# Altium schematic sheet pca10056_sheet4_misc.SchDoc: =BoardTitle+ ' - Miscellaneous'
size A3; Organization: Nordic Semiconductor; DocumentNumber: 4; SheetNumber: 4; SheetTotal: 6; CompanyName: Nordic Semiconductor; DocumentSize: A3
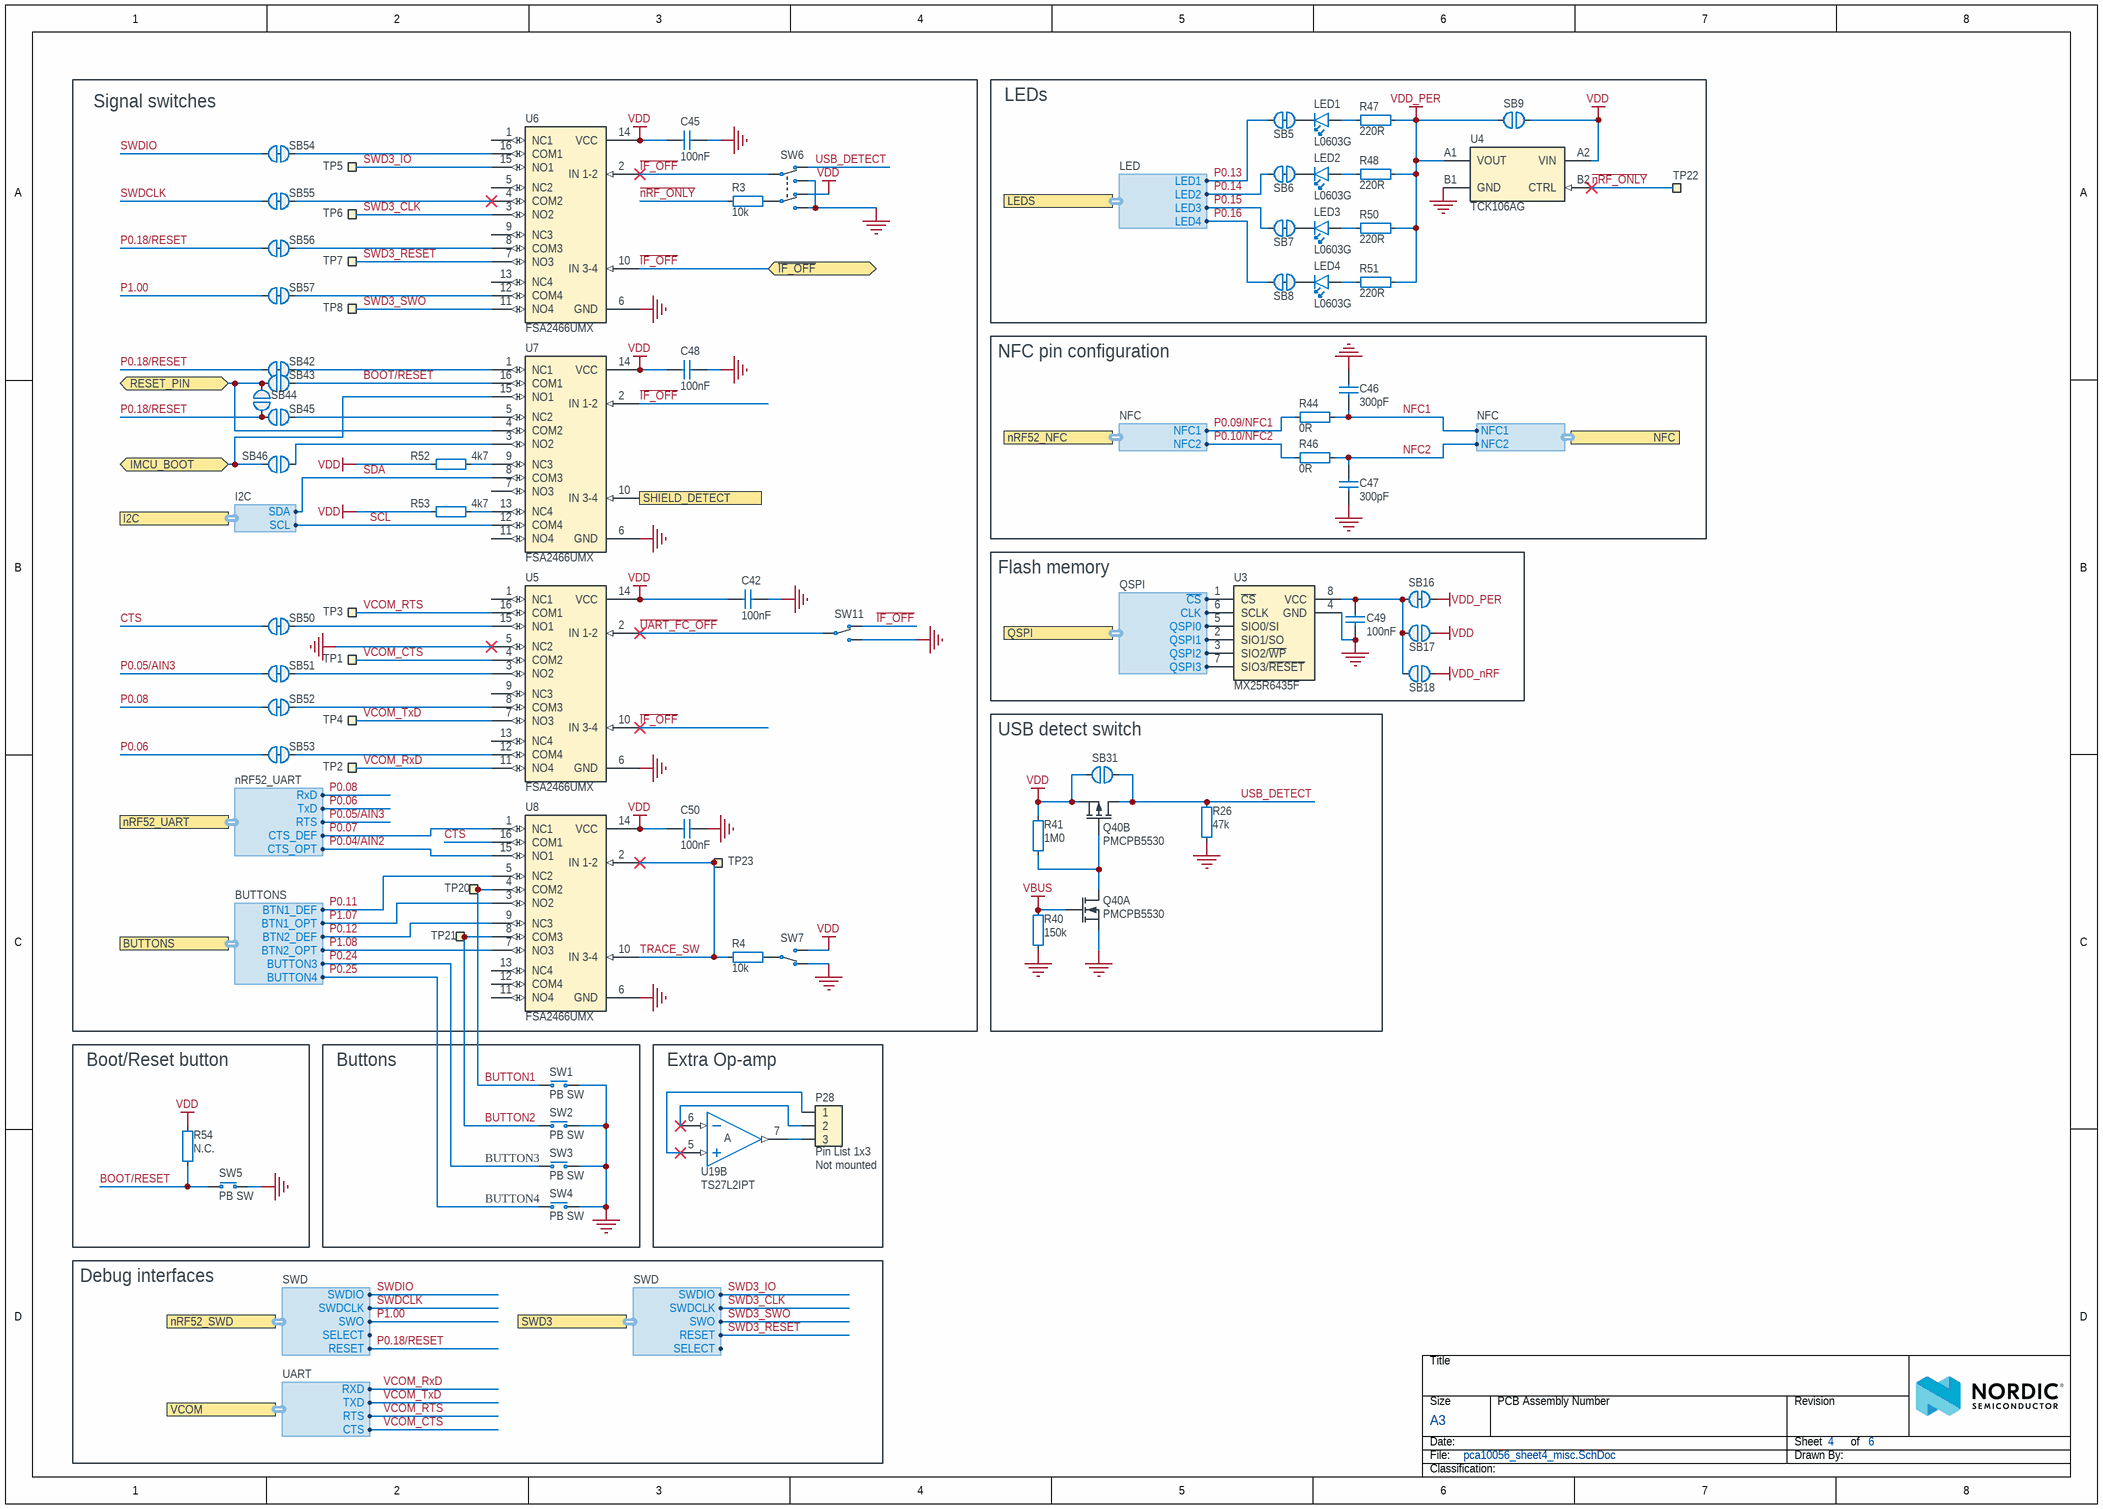
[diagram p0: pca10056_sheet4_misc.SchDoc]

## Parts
C42  100nF  [CAPC0603X03L_C]
C45  100nF  [CAPC0603X03L_C]
C46  300pF  [CAPC1005X04L]
C47  300pF  [CAPC1005X04L]
C48  100nF  [CAPC0603X03L_C]
C49  100nF  [CAPC0603X03L_C]
C50  100nF  [CAPC0603X03L_C]
LED1  L0603G  [LED_0603_G]
LED2  L0603G  [LED_0603_G]
LED3  L0603G  [LED_0603_G]
LED4  L0603G  [LED_0603_G]
P28  Pin List 1x3  Assembly: Not mounted  [LIST_1x3-NC]
Q40  PMCPB5530  [PMCPB5530X]  (parts A,B of 2)
R3  10k  [RESC0603X03L_C]
R4  10k  [RESC0603X03L_C]
R26  47k  [RESC0603X03L_C]
R40  150k  [RESC0603X03L_C]
R41  1M0  [RESC0603X03L_C]
R44  0R  [RESC1005X04L]
R46  0R  [RESC1005X04L]
R47  220R  [RESC0603X03L_C]
R48  220R  [RESC0603X03L_C]
R50  220R  [RESC0603X03L_C]
R51  220R  [RESC0603X03L_C]
R52  4k7  [RESC0603X03L_C]
R53  4k7  [RESC0603X03L_C]
R54  N.C.  [RESC0603X03L_C_NC]
SB5  Solderbridge  [Solderbridge_Shorted]  (value not drawn)  (net tie, no BOM)
SB6  Solderbridge  [Solderbridge_Shorted]  (value not drawn)  (net tie, no BOM)
SB7  Solderbridge  [Solderbridge_Shorted]  (value not drawn)  (net tie, no BOM)
SB8  Solderbridge  [Solderbridge_Shorted]  (value not drawn)  (net tie, no BOM)
SB9  Solderbridge  [Solderbridge]  (value not drawn)  (no BOM)
SB16  Solderbridge  [Solderbridge_Shorted]  (value not drawn)  (net tie, no BOM)
SB17  Solderbridge  [Solderbridge]  (value not drawn)  (no BOM)
SB18  Solderbridge  [Solderbridge]  (value not drawn)  (no BOM)
SB31  Solderbridge  [Solderbridge]  (value not drawn)  (no BOM)
SB42  Solderbridge  [Solderbridge_Shorted]  (value not drawn)  (net tie, no BOM)
SB43  Solderbridge  [Solderbridge]  (value not drawn)  (no BOM)
SB44  Solderbridge  [Solderbridge]  (value not drawn)  (no BOM)
SB45  Solderbridge  [Solderbridge]  (value not drawn)  (no BOM)
SB46  Solderbridge  [Solderbridge]  (value not drawn)  (no BOM)
SB50  Solderbridge  [Solderbridge_Shorted]  (value not drawn)  (net tie, no BOM)
SB51  Solderbridge  [Solderbridge_Shorted]  (value not drawn)  (net tie, no BOM)
SB52  Solderbridge  [Solderbridge_Shorted]  (value not drawn)  (net tie, no BOM)
SB53  Solderbridge  [Solderbridge_Shorted]  (value not drawn)  (net tie, no BOM)
SB54  Solderbridge  [Solderbridge_Shorted]  (value not drawn)  (net tie, no BOM)
SB55  Solderbridge  [Solderbridge_Shorted]  (value not drawn)  (net tie, no BOM)
SB56  Solderbridge  [Solderbridge_Shorted]  (value not drawn)  (net tie, no BOM)
SB57  Solderbridge  [Solderbridge_Shorted]  (value not drawn)  (net tie, no BOM)
SW1  PB SW  [Switch-PB-6.2x6.3mm-SMD]
SW2  PB SW  [Switch-PB-6.2x6.3mm-SMD]
SW3  PB SW  [Switch-PB-6.2x6.3mm-SMD]
SW4  PB SW  [Switch-PB-6.2x6.3mm-SMD]
SW5  PB SW  [Switch-PB-6.2x6.3mm-SMD]
SW6  MKH-22D14-G2-B  [MKH-22D14-G2-B]  (value not drawn)
SW7  Switch  [CJS-120xA]  (value not drawn)
SW11  Switch  [CJS-120xA]  (value not drawn)
TP1  Ø1.0mm,SMD  [TP_SMD_D1.0mm]  (value not drawn)  (no BOM)
TP2  Ø1.0mm,SMD  [TP_SMD_D1.0mm]  (value not drawn)  (no BOM)
TP3  Ø1.0mm,SMD  [TP_SMD_D1.0mm]  (value not drawn)  (no BOM)
TP4  Ø1.0mm,SMD  [TP_SMD_D1.0mm]  (value not drawn)  (no BOM)
TP5  Ø1.0mm,SMD  [TP_SMD_D1.0mm]  (value not drawn)  (no BOM)
TP6  Ø1.0mm,SMD  [TP_SMD_D1.0mm]  (value not drawn)  (no BOM)
TP7  Ø1.0mm,SMD  [TP_SMD_D1.0mm]  (value not drawn)  (no BOM)
TP8  Ø1.0mm,SMD  [TP_SMD_D1.0mm]  (value not drawn)  (no BOM)
TP20  Ø1.0mm,SMD  [TP_SMD_D1.0mm]  (value not drawn)  (no BOM)
TP21  Ø1.0mm,SMD  [TP_SMD_D1.0mm]  (value not drawn)  (no BOM)
TP22  Ø1.0mm,SMD  [TP_SMD_D1.0mm]  (value not drawn)  (no BOM)
TP23  Ø1.0mm,SMD  [TP_SMD_D1.0mm]  (value not drawn)  (no BOM)
U3  MX25R6435F  [SON127P600X80_HS-9N]
U4  TCK106AG  [BGA4C40P2X2_76X76X62]
U5  FSA2466UMX  [XQFN40P180X260X50-16N]
U6  FSA2466UMX  [XQFN40P180X260X50-16N]
U7  FSA2466UMX  [XQFN40P180X260X50-16N]
U8  FSA2466UMX  [XQFN40P180X260X50-16N]
U19  TS27L2IPT  [TSOP65P640X120-8N]  (part B of 2)

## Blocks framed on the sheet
Signal switches: C42 C45 C48 C50 R3 R4 R52 R53 SB42-SB46 SB50-SB57 SW6 SW7 SW11 TP1-TP8 TP20 TP21 TP23 U5-U8
LEDs: LED1-LED4 R47 R48 R50 R51 SB5-SB9 TP22 U4
NFC pin configuration: C46 C47 R44 R46
Flash memory: C49 SB16-SB18 U3
USB detect switch: Q40 R26 R40 R41 SB31
Boot/Reset button: R54 SW5
Buttons: SW1-SW4
Extra Op-amp: P28 U19

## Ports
BUTTONS (harness BUTTONS), I2C (harness I2C), IMCU_BOOT (bidir), LEDS (harness LED), NFC (harness NFC), nRF52_NFC (harness NFC), nRF52_SWD (harness SWD), nRF52_UART (harness nRF52_UART), QSPI (harness QSPI), RESET_PIN (bidir), SHIELD_DETECT (in), SWD3 (harness SWD), VCOM (harness UART), ~{IF_OFF} (bidir)

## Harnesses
SWD: SWDIO, SWDCLK, SWO, RESET, SELECT
NFC: NFC2, NFC1
I2C: SCL, SDA
UART: RTS, CTS, RXD, TXD
QSPI: ~{CS}, QSPI0, CLK, QSPI1, QSPI2, QSPI3
LED: LED4, LED3, LED2, LED1
BUTTONS: BTN2_OPT, BTN2_DEF, BTN1_OPT, BTN1_DEF, BUTTON3, BUTTON4
nRF52_UART: RTS, CTS_DEF, CTS_OPT, TxD, RxD

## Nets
GND: C42.1 C45.1 C46.2 C47.1 C48.1 C49.1 C50.1 Q40.1(S1) R26.2 R40.2 SW1.1(N.O) SW2.1(N.O) SW3.1(N.O) SW4.1(N.O) SW5.1(N.O) SW6.1(N.O-1) SW6.4(N.O-2) SW7.1(N.C) SW11.3(N.O) U3.4(GND) U3.9(GND) U4.B1(GND) U5.5(NC2) U5.6(GND) U6.6(GND) U7.6(GND) U8.6(GND)
VBUS: Q40.2(G1) R40.1
VDD: C42.2 C45.2 C48.2 C50.2 Q40.4(S2) R41.1 R52.1 R53.1 R54.2 SB9.1 SB17.1 SB31.1 SW6.6(N.C-2) SW7.3(N.O) U4.A2(VIN) U5.14(VCC) U6.14(VCC) U7.14(VCC) U8.14(VCC)
VDD_nRF: SB18.1
VDD_PER: R47.2 R48.2 R50.2 R51.2 SB9.2 SB16.1 U4.A1(VOUT)
BOOT/RESET: R54.1 SB43.1 SW5.2(COM) U7.16(COM1)
BUTTON1: SW1.2(COM) TP20.1 U8.4(COM2)
BUTTON2: SW2.2(COM) TP21.1 U8.8(COM3)
CTS: SB50.1 U8.16(COM1)
~{IF_OFF}: SW6.2(COM-1) SW11.1(N.C) U5.10(IN_3-4) U6.2(IN_1-2) U6.10(IN_3-4) U7.2(IN_1-2) ; port ~{IF_OFF}
IMCU_BOOT: SB46.2 U7.15(NO1) ; port IMCU_BOOT
~{nRF_ONLY}: R3.1 TP22.1 U4.B2(CTRL)
NFC1: C46.1 R44.1 ; port NFC.NFC1
NFC2: C47.2 R46.1 ; port NFC.NFC2
P0.04/AIN2: U8.15(NO1) ; port nRF52_UART.CTS_OPT
P0.05/AIN3: SB51.1 ; port nRF52_UART.RTS
P0.06: SB53.1 ; port nRF52_UART.TxD
P0.07: U8.1(NC1) ; port nRF52_UART.CTS_DEF
P0.08: SB52.1 ; port nRF52_UART.RxD
P0.09/NFC1: R44.2 ; port nRF52_NFC.NFC1
P0.10/NFC2: R46.2 ; port nRF52_NFC.NFC2
P0.11: U8.5(NC2) ; port BUTTONS.BTN1_DEF
P0.12: U8.9(NC3) ; port BUTTONS.BTN2_DEF
P0.13: SB5.1 ; port LEDS.LED1
P0.14: SB6.1 ; port LEDS.LED2
P0.15: SB7.1 ; port LEDS.LED3
P0.16: SB8.1 ; port LEDS.LED4
P0.18/RESET: SB42.2 SB44.2 SB45.2 SB56.1 ; port nRF52_SWD.RESET
P0.24: SW3.2(COM) ; port BUTTONS.BUTTON3
P0.25: SW4.2(COM) ; port BUTTONS.BUTTON4
P1.00: SB57.1 ; port nRF52_SWD.SWO
P1.07: U8.3(NO2) ; port BUTTONS.BTN1_OPT
P1.08: U8.7(NO3) ; port BUTTONS.BTN2_OPT
RESET_PIN: SB43.2 SB44.1 U7.4(COM2) ; port RESET_PIN
SCL: U7.12(COM4) ; port I2C.SCL
SDA: U7.8(COM3) ; port I2C.SDA
SHIELD_DETECT: U7.10(IN_3-4) ; port SHIELD_DETECT
SWD3_CLK: TP6.1 U6.3(NO2) ; port SWD3.SWDCLK
SWD3_IO: TP5.1 U6.15(NO1) ; port SWD3.SWDIO
SWD3_RESET: TP7.1 U6.7(NO3) ; port SWD3.RESET
SWD3_SWO: TP8.1 U6.11(NO4) ; port SWD3.SWO
SWDCLK: SB55.1 ; port nRF52_SWD.SWDCLK
SWDIO: SB54.1 ; port nRF52_SWD.SWDIO
TRACE_SW: R4.1 TP23.1 U8.2(IN_1-2) U8.10(IN_3-4)
~{UART_FC_OFF}: SW11.2(COM) U5.2(IN_1-2)
USB_DETECT: Q40.3(D2) R26.1 SB31.2 SW6.3(N.C-1)
VCOM_CTS: TP1.1 U5.4(COM2) ; port VCOM.CTS
VCOM_RTS: TP3.1 U5.16(COM1) ; port VCOM.RTS
VCOM_RxD: TP2.1 U5.11(NO4) ; port VCOM.RXD
VCOM_TxD: TP4.1 U5.7(NO3) ; port VCOM.TXD
NetC49_2: C49.2 SB16.2 SB17.2 SB18.2 U3.8(VCC)
NetLED1_1: LED1.1(C) SB5.2
NetLED1_2: LED1.2(A) R47.1
NetLED2_1: LED2.1(C) SB6.2
NetLED2_2: LED2.2(A) R48.1
NetLED3_1: LED3.1(C) SB7.2
NetLED3_2: LED3.2(A) R50.1
NetLED4_1: LED4.1(C) SB8.2
NetLED4_2: LED4.2(A) R51.1
NetP28_1: P28.1 U19.5(IN2+)
NetP28_2: P28.2 U19.6(IN2-)
NetP28_3: P28.3 U19.7(OUT2)
NetQ40_5: Q40.5(G2) Q40.6(D1) R41.2
NetR3_2: R3.2 SW6.5(COM-2)
NetR4_2: R4.2 SW7.2(COM)
NetR52_2: R52.2 U7.9(NC3)
NetR53_2: R53.2 U7.13(NC4)
NetSB42_1: SB42.1 U7.1(NC1)
NetSB45_1: SB45.1 U7.5(NC2)
NetSB46_1: SB46.1 U7.3(NO2)
NetSB50_2: SB50.2 U5.15(NO1)
NetSB51_2: SB51.2 U5.3(NO2)
NetSB52_2: SB52.2 U5.8(COM3)
NetSB53_2: SB53.2 U5.12(COM4)
NetSB54_2: SB54.2 U6.16(COM1)
NetSB55_2: SB55.2 U6.4(COM2)
NetSB56_2: SB56.2 U6.8(COM3)
NetSB57_2: SB57.2 U6.12(COM4)
NetU3_1: U3.1(~{CS}) ; port QSPI.~{CS}
NetU3_2: U3.2(SIO1/SO) ; port QSPI.QSPI1
NetU3_3: U3.3(SIO2/~{WP}) ; port QSPI.QSPI2
NetU3_5: U3.5(SIO0/SI) ; port QSPI.QSPI0
NetU3_6: U3.6(SCLK) ; port QSPI.CLK
NetU3_7: U3.7(SIO3/~{RESET}) ; port QSPI.QSPI3

Not connected (* = marked no-connect by the designer): U5 1(NC1) 9(NC3) 13(NC4); U6 1(NC1) 5(NC2) 9(NC3) 13(NC4); U7 7(NO3) 11(NO4); U8 11(NO4) 12(COM4) 13(NC4)

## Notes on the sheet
- BUTTON3
- BUTTON4
- Debug interfaces

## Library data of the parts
C42 C45 C48-C50 = C0201-100n: Capacitor, X5R, ±10%; Manufacturer: N.A.; Part number IPS: 00000001248, 00000002505; Part number Norautron: 262071862; Part number NEMS: 100200078; Note: 16V; Pad Count: 2; Component Status: Active
C46 C47 = C0402-300p: Capacitor, C0G, ±5%, 50V; Manufacturer: N.A.; Part number IPS: 00000007788; Part number NEMS: 100200155; Artikkelnr Noca: 20020004; Pad Count: 2; Component Status: Active
LED1-LED4 = VS 25C7M5: LED, Green, 0603, 573nm, Vf=2.0V, 24mcd, - 40 to +85°C; Manufacturer: Victory Electronics; Part number IPS: 00000001274, 00000009961; Part number Norautron: 26313411; Part number NEMS: 101400097; Note: N.A.; Artikkelnr Noca: 13019193; Pad Count: 2; Component Status: Active
P28 = Pin List 1x3, N.C.: Pin List 1x3, 2.54mm (100mil); Manufacturer: N.A.; Part number NEMS: 100500305; Pad Count: 3; Component Status: Active; System: Connector
Q40 = PMCPB5530X,115: Mosfet Array N and P-Channel 20V 4A (Ta), 3.4A (Ta) 490mW Surface Mount 6-HUSON-EP (2x2); Manufacturer: Nexperia; Part number IPS: 00000001918; Part number NEMS: 101300165; Note: N.A.; Pad Count: 8; Component Status: Active
R3 R4 = R0201-10k: Resistor, ±1%, 0.05W; Manufacturer: N.A.; Part number IPS: 00000001255; Part number Norautron: 26107101; Part number NEMS: 100100065; Note: Chip Res 1%; Pad Count: 2; Component Status: Active
R26 = R0201-47k: Resistor, ±1%, 0.05W; Manufacturer: N.A.; Part number IPS: 00000001423; Part number NEMS: 100100076; Note: Chip Res 1%; Pad Count: 2; Component Status: Active
R40 = R0201-150k: Resistor, ±1%, 0.05W; Manufacturer: N.A.; Part number IPS: 00000001422; Part number NEMS: 100100082; Note: Chip Res 1%; Pad Count: 2; Component Status: Active
R41 = R0201-1M0: Resistor, ±1%, 0.05W; Manufacturer: N.A.; Part number IPS: 00000001418; Part number Norautron: 26107108; Part number NEMS: 100100093; Note: Chip Res 1%; Pad Count: 2; Component Status: Active
R44 R46 = R0402-0R: Resistor, ±5%, 0.063W; Manufacturer: N.A.; Part number IPS: 00000007128; Part number NEMS: 100100109; Note: Chip Res 5%; Artikkelnr Noca: 27049000; Pad Count: 2; Component Status: Active
R47 R48 R50 R51 = R0201-220: Resistor, ±1%, 0.05W; Manufacturer: N.A.; Part number IPS: 00000000863; Part number Norautron: 26107014; Part number NEMS: 100100032; Note: Chip Res 1%; Pad Count: 2; Component Status: Active
R52 R53 = R0201-4k7: Resistor, ±1%, 0.05W; Manufacturer: N.A.; Part number IPS: 00000001706; Part number NEMS: 100100061; Note: Chip Res 1%; Pad Count: 2; Component Status: Active
R54 = R0201-N.C.: Not mounted; Manufacturer: N.A.; Part number NEMS: 100100107; Note: Chip Res; Assembly: Not mounted; Pad Count: 2; Component Status: Active
SB5-SB8 SB16 SB42 SB50-SB57 = Solderbridge Shorted: Shorted Solderbridge; Manufacturer: N.A.; Part number NEMS: 100500459; Pad Count: 2; Component Status: Active; System: Connector
SB9 SB17 SB18 SB31 SB43-SB46 = Solderbridge: Manufacturer: N.A.; Part number NEMS: 100500458; Pad Count: 2; Component Status: Active; System: Connector
SW1-SW5 = Switch-PB-6.2x6.3mm-SMD: Tactile Switch, SPNO, SMD, 160gf, 6.2x6.3x2.5mm; Manufacturer: Dailywell; Manufacturer Part Number: TS604VM1-025BR-R; Part number IPS: 00000007812; Part number NEMS: 101500001, 101500133; Note: N.A.; Artikkelnr Noca: 50019106; Pad Count: 4; Component Status: Active
SW6 = MKH-22D14-G2-B: Slide Switch DPDT; Manufacturer: Dailywell; Part number IPS: 00000004369; Part number NEMS: 101500096; Note: N.A.; Artikkelnr Noca: 50019112; Pad Count: 6; Component Status: Active
SW7 = CJS-1200TA: SMD slide Switch (ON-ON); Manufacturer: Copal Electronics Inc; Part number IPS: 00000009982; Part number Norautron: 26030738; Part number NEMS: 101500005; Note: N.A.; Artikkelnr Noca: 50019068; Pad Count: 3; Component Status: Active
SW11 = CJS-1200TA: SMD slide Switch (ON-ON); Manufacturer: Copal Electronics Inc; Part number IPS: 00000009982; Part number Norautron: 26030738; Part number NEMS: 101500005; Pad Count: 3; Note: N.A.; Artikkelnr Noca: 50019068; Component Status: Active
TP1-TP8 TP20-TP23 = TP_SMD_Ø1.0MM: 1.0mm circular SMD testpad; Manufacturer: Nordic Semiconductor; Manufacturer Part Number: N.A.; Part number NEMS: 100500475; Pad Count: 1; Component Status: Active
U3 = MX25R6435FZNIL0: Ultra low power, 64M-bit, serial multi I/O flash memory; Manufacturer: Macronix; Part number IPS: 00000004370; Part number NEMS: 101900438; Note: N.A.; Artikkelnr Noca: 15020015; Pad Count: 8; Component Status: Active
U4 = TCK106AG: 1.0 A Load Switch IC with Slew Rate Control Driver in Ultra Small Package; Manufacturer: Toshiba; Manufacturer Part Number: TCK106AG,LF; Part number IPS: 00000004390; Part number Norautron: 26500627; Part number NEMS: 101900575; Note: N.A.; Pad Count: 4; Component Status: Active
U5-U8 = FSA2466UMX: Data / Audio Low-Voltage Dual DPDT Analog Switch; Manufacturer: ON Semiconductor; Part number IPS: 00000009986; Part number Norautron: 26500608; Part number NEMS: 101900422; Note: N.A.; Artikkelnr Noca: 15070069; Pad Count: 16; Component Status: Active
U19 = TS27L2IPT: Precision very low power CMOS dual operational amplifier; Manufacturer: STMicroelectronics; Part number IPS: 00000009991; Part number NEMS: 101900442; Note: N.A.; Artikkelnr Noca: 17010019; Pad Count: 8; Component Status: Active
